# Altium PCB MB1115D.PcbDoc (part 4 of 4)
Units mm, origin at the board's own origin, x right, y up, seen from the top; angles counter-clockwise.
Board outline 66 x 97 mm, 2 copper layers (TOP, Bottom), stack 1.535 mm thick; 198 components, 186 nets, 760 pads, 493 vias.
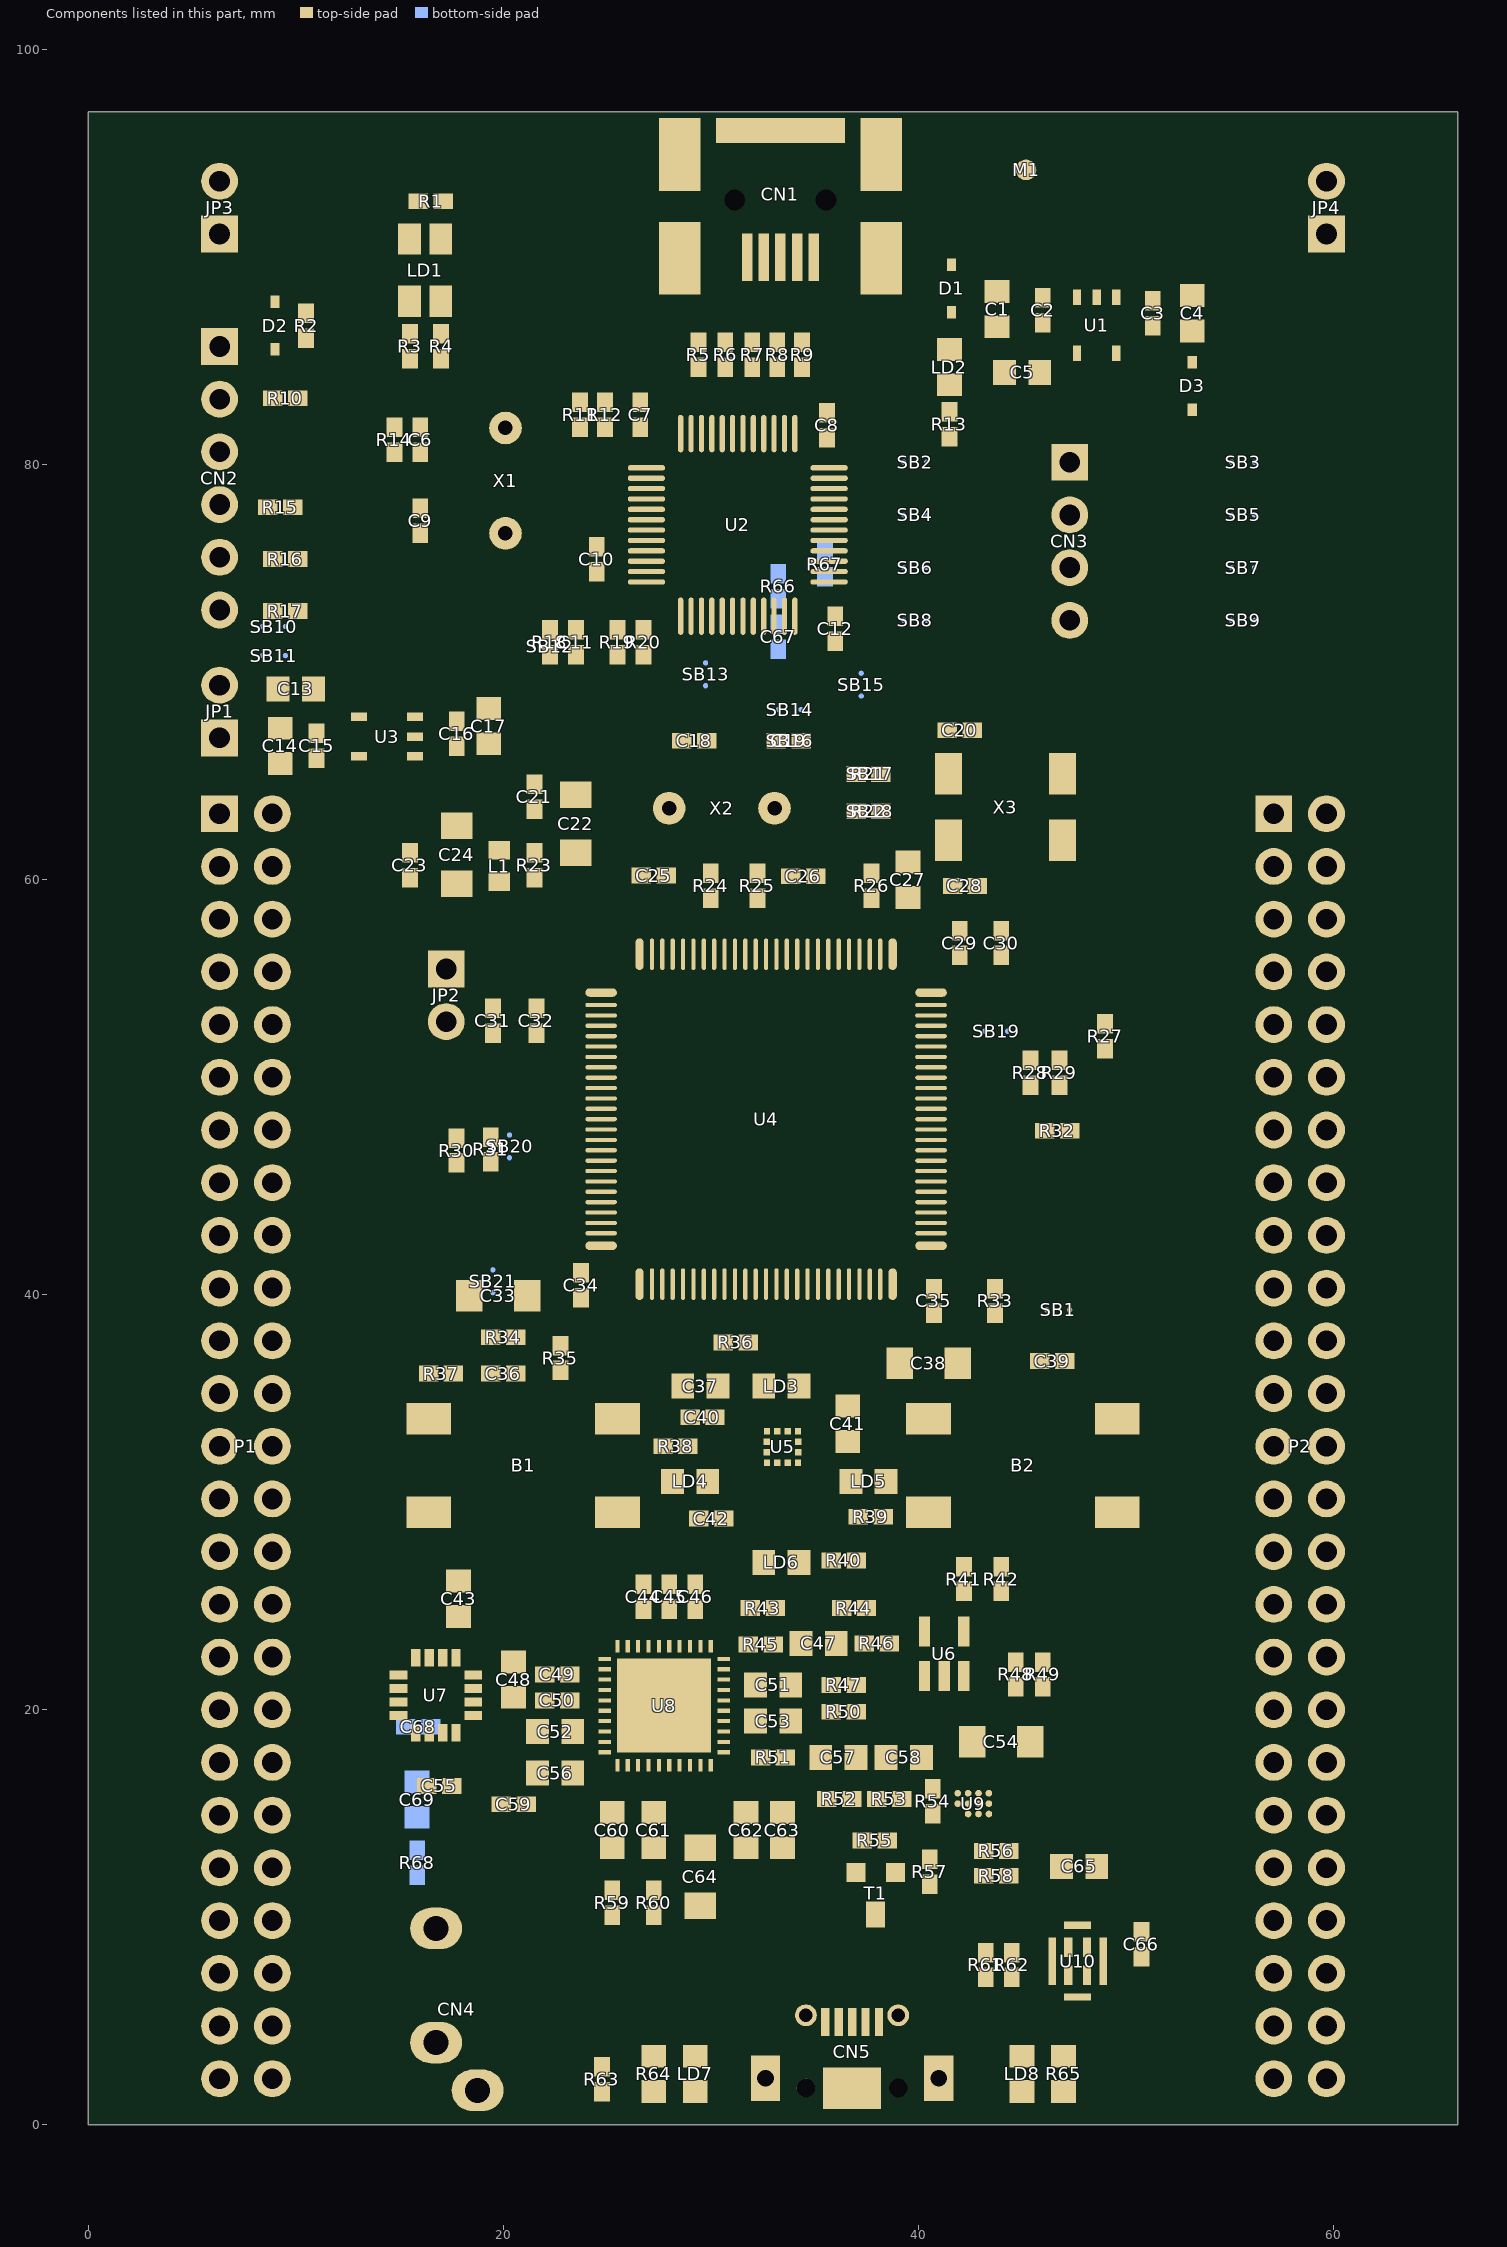
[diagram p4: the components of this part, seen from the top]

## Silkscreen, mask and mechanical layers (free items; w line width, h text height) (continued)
CARTOUCHE F1:
  region: 101.58,-105.73 107.41,-105.727 107.676,-105.197 105.39,-102.911 105.085,-102.225 105.085,-101.387 105.161,-101.082 105.466,-100.548 105.771,-100.244 106.152,-100.015 106.609,-99.863 107.143,-99.786 117.963,-99.786 117.353,-101.387 117.277,-101.463 114.763,-101.463 112.324,-107.254 110.572,-107.254 112.934,-101.691 112.934,-101.463 106.914,-101.463 106.762,-101.539 106.685,-101.691 106.685,-101.92 106.762,-101.996 108.971,-104.13 109.2,-104.511 109.276,-104.892 109.352,-104.968 109.352,-105.654 cw(c107.079,-105.187) 108.133,-107.254 100.97,-107.254 100.97,-107.102 101.504,-105.806
  lines w0.203: -21.293,-115.155 87.927,-115.155 ; -21.293,-106.265 87.927,-106.265 ; 100.97,-107.254 101.123,-107.406 113.696,-107.406 ccw(c113.131,-104.943) 115.372,-106.111 118.42,-98.796 118.42,-98.491 118.344,-98.415 105.695,-98.415 ccw(c106.188,-100.786) 104.018,-99.71 100.97,-107.102 100.97,-107.254
  lines w0.508: -58.123,-122.775 -58.123,-82.135 132.377,-82.135 ; -55.583,-107.535 -25.103,-107.535 ; -55.583,-96.105 -25.103,-96.105 ; -67.623,-122.775 -67.623,164.225 132.377,164.225 132.377,-122.775 -67.623,-122.775 ; -55.583,-120.235 -25.103,-120.235 -25.103,-84.675 -55.583,-84.675 -55.583,-120.235 ; -22.563,-120.235 -22.563,-97.375 89.197,-97.375 89.197,-120.235 -22.563,-120.235 ; -22.563,-94.835 89.197,-94.835 89.197,-84.675 -22.563,-84.675 -22.563,-94.835 ; 91.737,-120.235 129.837,-120.235 129.837,-84.675 91.737,-84.675 91.737,-120.235
  text "DATE:" at -53.97,-89.82 h1.78
  text "25/05/2020" at -53.741,-94.103 h1.78
  text "STM32F411E-DISCOVERY" at -20.123,-105.275 h2.45
  text "MB1115D" at -20.123,-114.275 h2.45
CARTOUCHE FX:
  region: -36.803,-105.755 -42.634,-105.752 -42.899,-105.221 -40.613,-102.935 -40.308,-102.249 -40.308,-101.411 -40.385,-101.106 -40.689,-100.573 -40.994,-100.268 -41.375,-100.04 -41.832,-99.887 -42.366,-99.811 -53.186,-99.811 -52.577,-101.411 -52.5,-101.487 -49.986,-101.487 -47.547,-107.279 -45.795,-107.279 -48.157,-101.716 -48.157,-101.487 -42.137,-101.487 -41.985,-101.564 -41.909,-101.716 -41.909,-101.945 -41.985,-102.021 -44.195,-104.154 -44.423,-104.535 -44.499,-104.916 -44.576,-104.993 -44.576,-105.678 ccw(c-42.303,-105.211) -43.356,-107.279 -36.194,-107.279 -36.194,-107.126 -36.727,-105.831
  lines w0.203: -23.15,-115.18 86.07,-115.18 ; -23.15,-106.29 86.07,-106.29 ; -53.643,-98.82 -53.643,-98.516 -53.567,-98.439 -40.918,-98.439 cw(c-41.412,-100.811) -39.242,-99.735 -36.194,-107.126 -36.194,-107.279 -36.346,-107.431 -48.919,-107.431 cw(c-48.354,-104.967) -50.595,-106.136 -53.643,-98.82
  lines w0.508: -67.6,-82.16 122.9,-82.16 122.9,-122.8 ; 89.88,-107.56 120.36,-107.56 ; 89.88,-96.13 120.36,-96.13 ; -67.6,-122.8 -67.6,164.2 132.4,164.2 132.4,-122.8 -67.6,-122.8 ; -65.06,-120.26 -65.06,-84.7 -26.96,-84.7 -26.96,-120.26 -65.06,-120.26 ; -24.42,-120.26 87.34,-120.26 87.34,-97.4 -24.42,-97.4 -24.42,-120.26 ; -24.42,-94.86 87.34,-94.86 87.34,-84.7 -24.42,-84.7 -24.42,-94.86 ; 89.88,-120.26 120.36,-120.26 120.36,-84.7 89.88,-84.7 89.88,-120.26
  text "DATE:" at 118.777,-89.825 h1.78
  text "10/07/2013" at 118.777,-93.825 h1.5
  text "STM32F401C-DISCOVERY" at 84.9,-105.3 h2.45
  text "MB1115B" at 84.9,-114.3 h2.45
  text "S.M.E.E." at 116.867,-117.185 h3.5

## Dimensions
57.13,2.22 to 59.67,2.22 on MECHANICAL DRAWING
59.67,2.22 to 66,0 on MECHANICAL DRAWING
6.33,2.22 to 8.87,2.22 on User Attributes
6.33,2.22 to 0,0 on MECHANICAL DRAWING
0,97 to 0,0 on MECHANICAL DRAWING
66,97 to 66,0 on MECHANICAL DRAWING
6.33,93.66 to 0,97 on MECHANICAL DRAWING
0,0 to 6.33,2.22 on MECHANICAL DRAWING
59.67,93.66 to 66,97 on MECHANICAL DRAWING
6.33,63.18 to 6.33,93.66 on MECHANICAL DRAWING
6.33,2.22 to 0,0 on User Attributes
59.67,93.66 to 59.67,63.18 on MECHANICAL DRAWING
0,97 to 66,97 on MECHANICAL DRAWING
6.33,93.66 to 0,97 on MECHANICAL DRAWING
6.33,2.22 to 59.67,2.22 on MECHANICAL DRAWING
0,0 to 66,0 on User Attributes
6.33,2.22 to 59.67,2.22 on User Attributes
59.67,2.22 to 66,0.7 on User Attributes
59.67,2.22 to 66,0 on User Attributes
66,0 to 59.67,2.22 on MECHANICAL DRAWING
59.67,2.22 to 57.13,2.22 on User Attributes
59.67,63.18 to 66,97 on User Attributes
59.67,93.66 to 66,97 on MECHANICAL DRAWING
8.87,2.22 to 6.33,2.22 on MECHANICAL DRAWING
6.33,91.12 to 6.33,63.18 on User Attributes
59.67,91.12 to 59.67,63.18 on User Attributes
6.33,2.22 to 0,0 on User Attributes
6.33,93.66 to 59.67,93.66 on User Attributes
0,97 to 66,97 on User Attributes
6.33,93.66 to 0,97 on User Attributes
6.33,93.66 to 0,97 on User Attributes
66,97 to 59.67,93.66 on User Attributes
59.67,93.66 to 66,97 on User Attributes
0,97 to 0,0 on User Attributes
6.33,63.18 to 6.33,2.22 on User Attributes
59.67,63.18 to 59.67,2.22 on User Attributes
0,97 to 6.33,63.18 on User Attributes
